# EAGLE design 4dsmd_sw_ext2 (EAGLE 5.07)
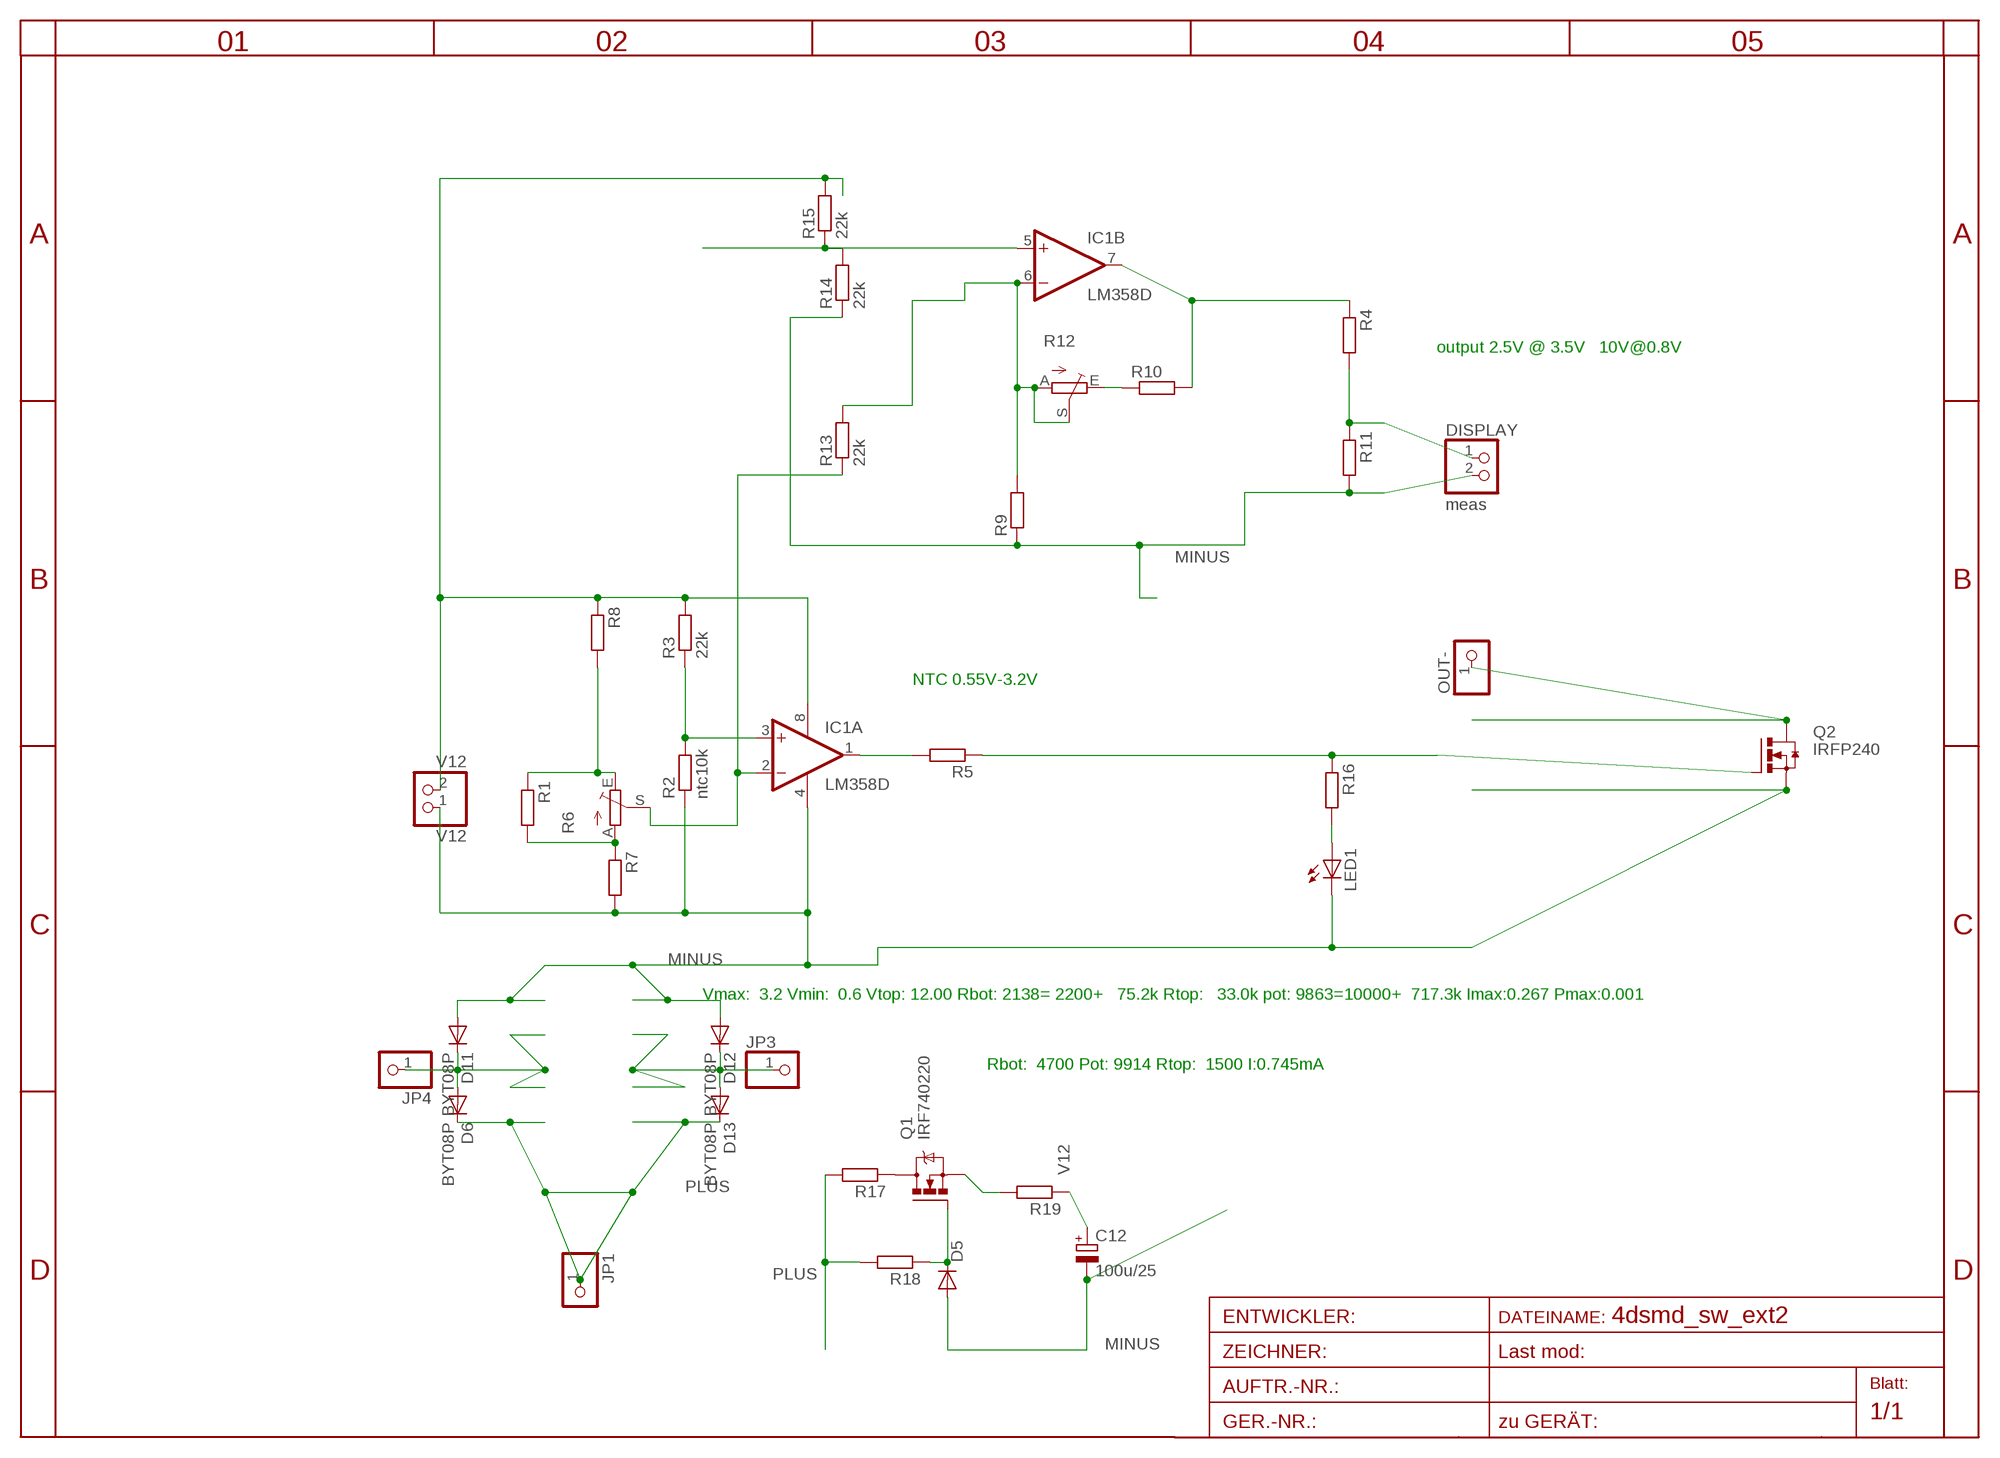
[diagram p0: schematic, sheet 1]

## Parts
C12  100u/25  CPOL-EUD  [PANASONIC_D]
D5  DIODE-MINIMELF  [MINIMELF]
D6  BYT08P  [TO220ACS]
D11  BYT08P  [TO220ACS]
D12  BYT08P  [TO220ACS]
D13  BYT08P  [TO220ACS]
DISPLAY  meas  PINHD-1X2STR  [1X02]
IC1  LM358D  [SO08]
JP1  PINHD-1X12MM2  [1X2MM2]
JP3  PINHD-1X12MM2  [1X2MM2]
JP4  PINHD-1X12MM2  [1X2MM2]
LED1  LEDSMT1206  [1206]
OUT-  PINHD-1X12MM2  [1X2MM2]
Q1  IRF740220  [TO220BV]
Q2  IRFP240  [TO247BV]
R1  R-EU_R1206  [R1206]
R2  ntc10k  R-EU_0204/5  [0204/5]
R3  22k  R-EU_R0805  [R0805]
R4  R-EU_R0805  [R0805]
R5  R-EU_0204/3  [0204/3]
R6  TRIM_EU-RAND160  [RANDL]
R7  R-EU_R1206  [R1206]
R8  R-EU_R1206  [R1206]
R9  R-EU_R0805  [R0805]
R10  R-EU_R0805  [R0805]
R11  R-EU_R0805  [R0805]
R12  TRIM_EU-CA6V  [CA6V]
R13  22k  R-EU_R0805  [R0805]
R14  22k  R-EU_R0805  [R0805]
R15  22k  R-EU_R0805  [R0805]
R16  R-EU_R1206  [R1206]
R17  R-EU_0207/10  [0207/10]
R18  R-EU_0207/10  [0207/10]
R19  R-EU_0207/12  [0207/12]
V12  V12  PINHD-1X2STR  [1X02]

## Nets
A: R1.2 R6.A R7.1
AC1: D6.A D11.C JP4.1
AC2: D12.C D13.A JP3.1
E: R1.1 R6.E R8.2
KKK: IC1.6(B:-IN) R9.2 R12.A R12.S R13.2
MINUS: C12.- D5.A D11.A D12.A DISPLAY.2 IC1.4(P:V-) LED1.C Q2.S R2.1 R7.2 R9.1 R11.2 R14.1 V12.1
N$1: DISPLAY.1 R4.2 R11.1
N$2: IC1.5(B:+IN) R14.2 R15.1
N$3: IC1.1(A:OUT) R5.2
N$4: R10.1 R12.E
N$5: IC1.3(A:+IN) R2.2 R3.1
N$6: Q2.G R5.1 R16.1
N$8: OUT-.1 Q2.D
N$9: IC1.2(A:-IN) R6.S R13.1
N$10: Q1.D R17.1
N$11: IC1.7(B:OUT) R4.1 R10.2
N$12: D5.C Q1.G R18.1
N$14: LED1.A R16.2
PLUS: D6.C D13.C JP1.1 R17.2 R18.2
S: IC1.8(P:V+) R3.2 R8.1 R15.2 V12.2
V12: C12.+ R19.1
WAE: Q1.S R19.2

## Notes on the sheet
- output 2.5V @ 3.5V   10V@0.8V
- NTC 0.55V-3.2V
- Vmax:  3.2 Vmin:  0.6 Vtop: 12.00 Rbot: 2138= 2200+   75.2k Rtop:   33.0k pot: 9863=10000+  717.3k Imax:0.267 Pmax:0.001
- Rbot:  4700 Pot: 9914 Rtop:  1500 I:0.745mA

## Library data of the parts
C12 = rcl:CPOL-EU: POLARIZED CAPACITOR, European symbol
D5 = diode:DIODE-: DIODE
D6 D11-D13 = diode:BYT08P: DIODE
DISPLAY V12 = pinhead:PINHD-1X2: PIN HEADER
IC1 = linear:LM358: OP AMP also LM158; LM258; LM2904 Source: http://cache.national.com/ds/LM/LM158.pdf
JP1 JP3 JP4 OUT- = pinhead:PINHD-1X1: PIN HEADER
LED1 = led:LED: LED
Q1 = transistor-power:IRF740: N-CHANNEL MOS FET
Q2 = transistor-power:IRFP240: HEXFET Power MosFet Source: http://www.irf.com/
R1-R5 R7-R11 R13-R19 = rcl:R-EU_: RESISTOR, European symbol
R6 R12 = pot:TRIM_EU-: POTENTIOMETER

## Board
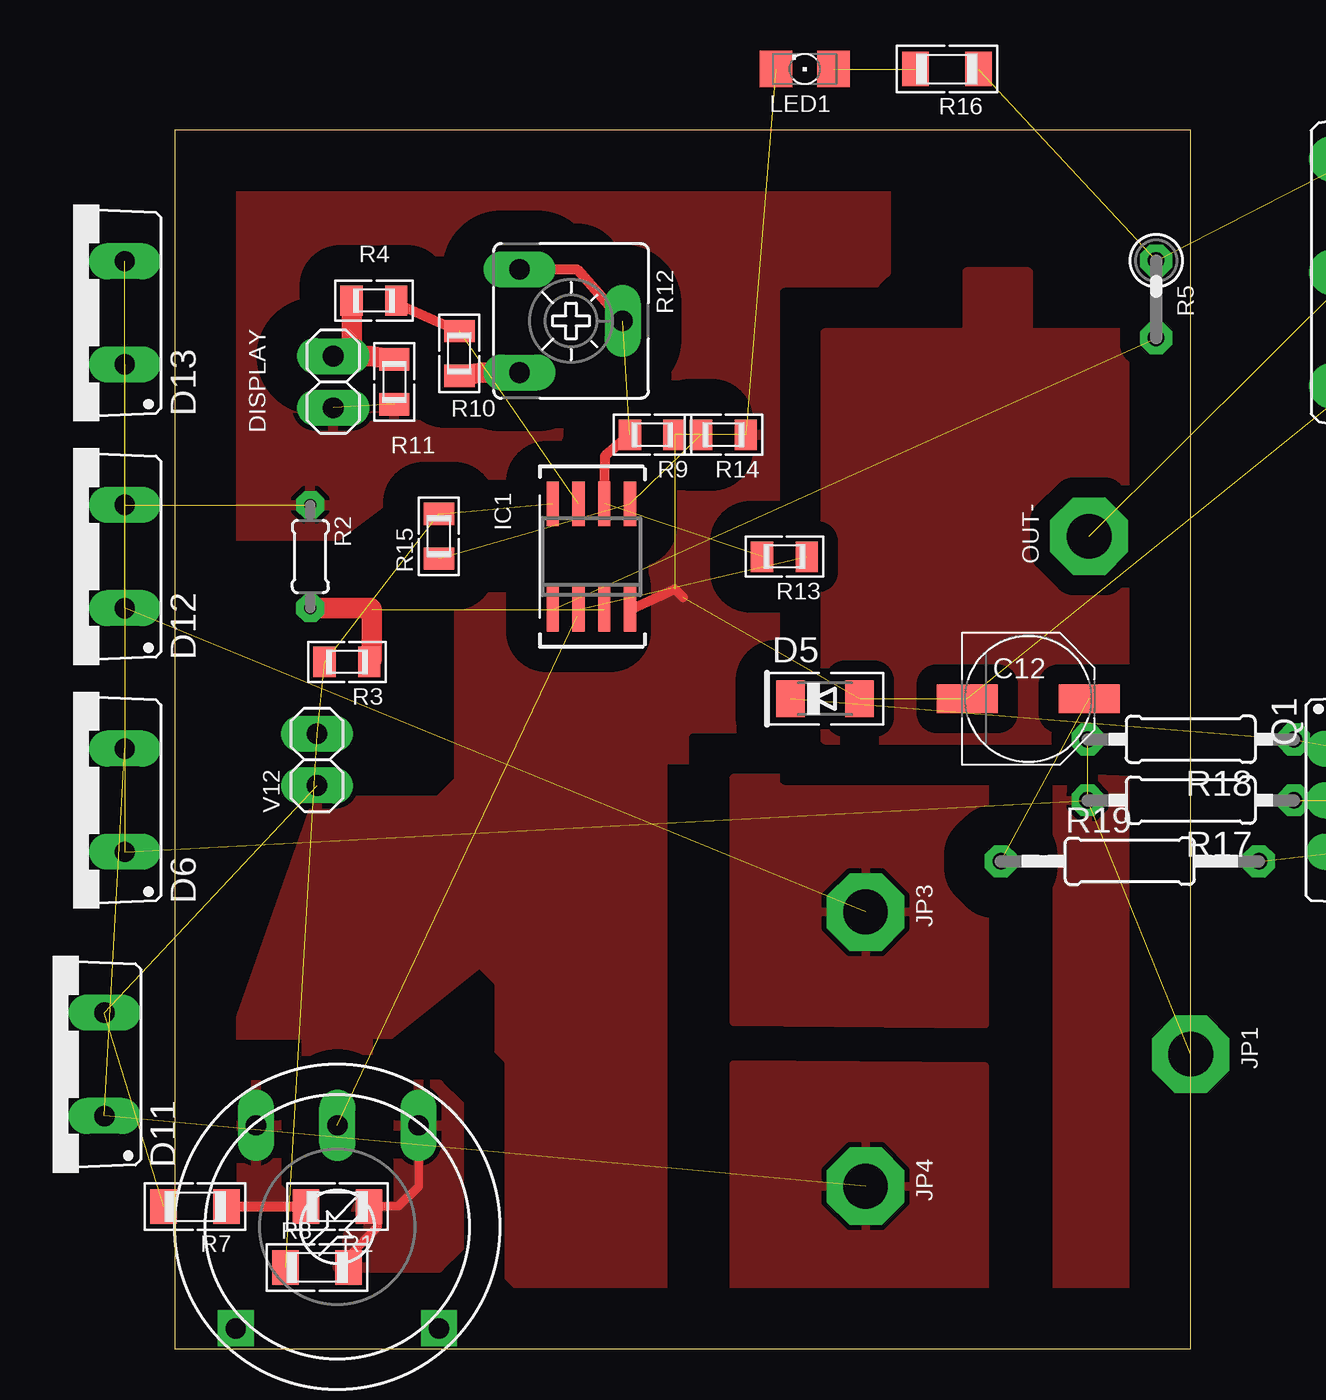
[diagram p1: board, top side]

Size 50 x 60 mm. Coordinates in mm from the lower left corner, seen from the top.
Outline: 0,0 50,0 50,60 0,60 0,0
Copper layers (1*16): Top 0.035mm / dielectric 1.5mm / Bottom 0.035mm
Design rules "default *": minimum track width 10mil, minimum drill 20mil, track to track 8mil, track to pad 8mil, pad to pad 8mil, via to via 8mil, smd to smd 8mil, copper to edge 3mm, drill to drill 8mil, minimum pad ring 15mil, minimum via ring 8mil, stop-mask expansion 4mil, vias tented up to drill 0mil, thermal gap 10mil

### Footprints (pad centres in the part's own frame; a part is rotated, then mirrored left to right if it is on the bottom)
PANASONIC_D = smd 3 x 1.4: + 3,0; - -3,0
MINIMELF = smd 1.4 x 1.8: A 1.7,0; C -1.7,0
TO220ACS = drill 1 pad 1.676 long: A 2.54,-2.54; C -2.54,-2.54
1X02 = drill 1.016 pad 1.676 long: 1 -1.27,0; 2 1.27,0
SO08 = smd 0.6 x 2.2: 1 -1.905,-2.6; 2 -0.635,-2.6; 3 0.635,-2.6; 4 1.905,-2.6; 5 1.905,2.6; 6 0.635,2.6; 7 -0.635,2.6; 8 -1.905,2.6
1X2MM2 = drill 2.2 pad 3.81 octagon: 1 0,0
1206 = smd 1.6 x 1.803: A -1.422,0; C 1.422,0
TO220BV = drill 1.016 long: D 0,-2.54; G -2.54,-2.54; S 2.54,-2.54
TO247BV = drill 1.499 long: D 0,-2.921; G -5.588,-2.921; S 5.588,-2.921
R1206 = smd 1.3 x 1.7: 1 -1.55,0; 2 1.55,0
0204/5 = drill 0.6 octagon: 1 -2.54,0; 2 2.54,0
R0805 = smd 1.1 x 1.5: 1 -1.1,0; 2 1.1,0
0204/3 = drill 0.813 octagon: 1 -1.27,0; 2 2.54,0
RANDL = drill 1 long: A -4,5; E 4,5; S 0,5 | drill 1 square: P$1 -5,-5; P$2 5,-5
CA6V = drill 1.016 long: A -2.54,-2.54; E 2.54,-2.54; S 0,2.54
0207/10 = drill 0.8 octagon: 1 -5.08,0; 2 5.08,0
0207/12 = drill 0.813 octagon: 1 -6.35,0; 2 6.35,0

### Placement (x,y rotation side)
C12  42,32 0 top
D5  32,32 0 top
D6  -5,27 90 top
D11  not placed on the board
D12  -5,39 90 top
D13  -5,51 90 top
DISPLAY  7.8,47.6 270 top
IC1  20.5,39 0 top
JP1  50,14.5 270 top
JP3  34,21.5 270 top
JP4  34,8 270 top
LED1  31,63 180 top
OUT-  45,40 90 top
Q1  not placed on the board
Q2  not placed on the board
R1  8,7 180 top
R2  6.67,39 270 top
R3  8.47,33.81 180 top
R4  9.8,51.6 180 top
R5  48.3,52.3 270 top
R6  8,6 0 top
R7  1,7 180 top
R8  7,4 0 top
R9  23.5,45 180 top
R10  14,49 90 top
R11  10.8,47.6 270 top
R12  19.5,50.6 270 top
R13  30,39 180 top
R14  27,45 180 top
R15  13,40 90 top
R16  38,63 180 top
R17  50,27 180 top
R18  50,30 180 top
R19  47,24 0 top
V12  7,29 90 top

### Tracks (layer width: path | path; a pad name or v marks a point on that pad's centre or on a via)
A
  Top 0.5: R7.1 R1.2
  pour Top (isolate 1): 2,7 2,12 3,13 5,13 5,8 6,7
AC1  (2 unrouted)
  pour Top (isolate 2, rank 3): 27.5,14 39.86,13.9 39.86,1.47 27.5,1.5
AC2  (2 unrouted)
  pour Top (isolate 2, rank 3): 39.86,28.14 39.86,15.98 27.5,16.1 27.5,28.1
E
  Top 0.406: R8.2 8.55,4.55 10,6 10,6.55 R1.1 11,7 12,8 R6.E
  pour Top (isolate 1): 8,4 13,4 14,5 14,12 13,13 11,13 11,7 9,7
KKK  (2 unrouted)
  Top 0.5: IC1.6 21.18,43.98 R9.2 | R12.A 19.8,53.14 R12.S
MINUS  (10 unrouted)
  Top 0.5: IC1.4 24.6,37.4 25,37
  pour Top (isolate 2, rank 4): 3,57 35,57 35,53 34,52 31,52 31,30 30,29 24,29 24,3 17,3 16,4 16,18 15,19 0,7 7,27 13,27 14,28 14,37 17,37 20,40 20,42 19,43 12,43 8,40 3,40
N$1
  Top 1: R4.2 8.7,48.97 DISPLAY.1 9.63,48.87 R11.1
N$2  (2 unrouted)
N$3  (1 unrouted)
N$4
  Top 1: R12.E 15.16,48.06 R10.1
N$5  (1 unrouted)
  Top 1: R2.2 9.64,36.46 9.7,36.4 9.7,33.94 R3.1
N$6  (2 unrouted)
N$7
  pour Top (isolate 1): 39,52 39,50 32,50 32,30 48,30 48,50 42,50 42,53 39,53
N$8  (1 unrouted)
N$9  (2 unrouted)
  Top 0.406: IC1.2 19.8,36.06
N$10  (1 unrouted)
N$11  (1 unrouted)
  Top 0.5: R4.1 10.6,51.6 R10.2
N$12  (2 unrouted)
N$14  (1 unrouted)
PLUS  (4 unrouted)
  pour Top (isolate 2, rank 4): 50.71,27.86 51.29,1.74 43.4,1.74 43.4,28.14
S  (4 unrouted)
V12  (1 unrouted)
WAE  (1 unrouted)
